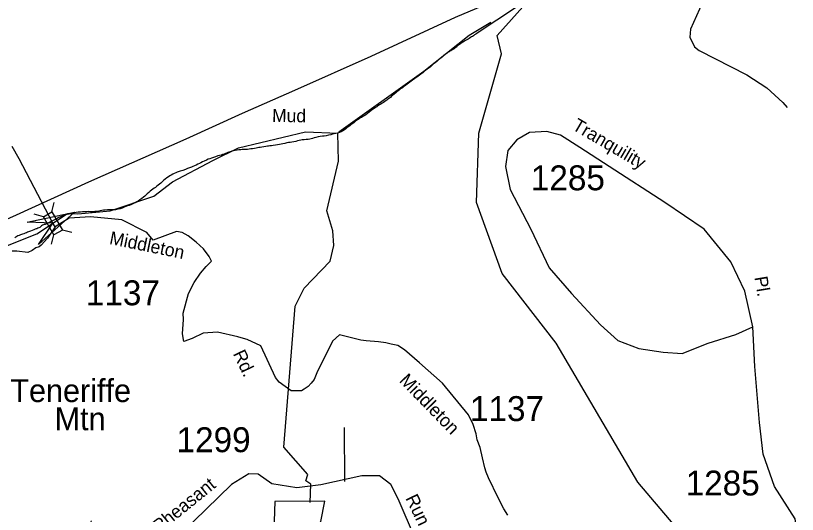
# Model space of a CAD drawing. Extents: x 884530 to 1028605, y 526725 to 653634.
# Drawn here: x 962593 to 966518, y 571686 to 574191 of the extents above; entities that cross this region are included whole.
import ezdxf

# ---------------------------------------------------------------- set-up
doc = ezdxf.new("R2010")
doc.units = 0
for name, color, linetype in [('Exist Boundary Political City Limit New', 7, 'Continuous'), ('Exist Geographical Mountain Summit Label', 7, 'Continuous'), ('Exist Hydrographic Bay Label', 7, 'Continuous'), ('Exist Hydrographic Creek Single Shore', 7, 'Continuous'), ('Exist Hydrographic Creek Single Shore Label', 7, 'Continuous'), ('Exist Road Non-System Type 51', 7, 'Continuous'), ('Exist Road Secondary Structure Standard Bridge Attributed CELL', 7, 'Continuous'), ('Exist Road Secondary Structure Standard Bridge CELL', 7, 'Continuous'), ('Exist Road Secondary Type 41 Attributed', 7, 'Continuous'), ('Exist Road Secondary Type 51 Attributed', 7, 'Continuous'), ('Exist Road Secondary Type 51 Label', 7, 'Continuous'), ('Exist Road Secondary Type 51 Number Label', 7, 'Continuous'), ('Exist Utilities Electrical Transmission Line', 7, 'Continuous'), ('Map Preparation Boundary City Limit Buffer Line', 7, 'Continuous')]:
    doc.layers.add(name, color=color, linetype=linetype)

msp = doc.modelspace()

# ---------------------------------------------------------------- linework, layer by layer
at = {"layer": 'Exist Boundary Political City Limit New'}
for points in [[(965107.1, 574233.1), (964910.9, 574103.4), (964908.8, 574101.8), (964903.6, 574098.1), (964897.6, 574094.1), (964891.6, 574090.1), (964886.4, 574086.7), (964881.7, 574083.8), (964876.3, 574080.5), (964870.5, 574077), (964864.4, 574073.3), (964858.1, 574069.4), (964852.1, 574065.7), (964846.6, 574062.4), (964842.1, 574059.9), (964834.9, 574055.7), (964826, 574049.9), (964816.9, 574043.4), (964808.9, 574037.1), (964804.4, 574033.1), (964799.5, 574029.1), (964794.4, 574024.9), (964788.8, 574020.9), (964783.7, 574017.7)], [(964783.7, 574017.7), (964778.6, 574014.8), (964773.8, 574012.1), (964769.8, 574009.9), (964765, 574007), (964759.5, 574003.2), (964754, 573999.1), (964749.1, 573995.2), (964742.8, 573990.2), (964736.1, 573984.9), (964729.2, 573979.1), (964722.4, 573973.6), (964714.7, 573967.2), (964707.6, 573961.4), (964700.9, 573955.9), (964695.1, 573950.9), (964690.2, 573946.5), (964684.6, 573941.6), (964678.9, 573936.6), (964673.8, 573932.4), (964669.2, 573929), (964664.2, 573925.4), (964658.7, 573921.4), (964653.1, 573917.3), (964645.9, 573911.7), (964639.1, 573906.1), (964632.8, 573900.9), (964627.2, 573896.4), (964620.4, 573891.4), (964612.2, 573885.8), (964603.9, 573880.1), (964596.7, 573874.9), (964591.3, 573870.9), (964585.4, 573866.4), (964579.2, 573861.6), (964572.8, 573856.7), (964565.6, 573851.4), (964558.4, 573846.4), (964551.6, 573841.6), (964545.5, 573837.2), (964540.5, 573833.5), (964534.9, 573829.2), (964529.4, 573825), (964524.5, 573821.3), (964519.3, 573817.4), (964513.6, 573813.1), (964507.4, 573808.3), (964501.2, 573803.3), (964494.2, 573797.3), (964487.4, 573791.4), (964480.9, 573785.8), (964474.9, 573780.7), (964470.4, 573777.1), (964465.3, 573773.2), (964460.4, 573769.6), (964456.2, 573766.4), (964451.6, 573763.1), (964446.1, 573759.4), (964440.1, 573755.4), (964433.5, 573751.1), (964426.7, 573746.8), (964420.2, 573742.6), (964414.7, 573739), (964410.7, 573736.4), (964406.2, 573733.6), (964400, 573729.5), (964392.6, 573724.7), (964384.7, 573719.4), (964376.1, 573712.6), (964367.6, 573705.9), (964359.3, 573699.6), (964351.2, 573693.6), (964346.1, 573690), (964340.3, 573686.2), (964334.8, 573682.9), (964330.1, 573680.2), (964325.1, 573677.5), (964319.2, 573674.1), (964313, 573670.1), (964306.6, 573665.8), (964298.2, 573659.4), (964290.4, 573653.1), (964283.2, 573647.1), (964276.8, 573641.9), (964270.6, 573637.4), (964263.4, 573632.1), (964256.2, 573626.8), (964250.2, 573621.9), (964243.8, 573616.9), (964236.2, 573612), (964227.8, 573607.5), (964218.5, 573603.6), (964209.2, 573600.8), (964200.1, 573598.5), (964191.7, 573596.8), (964184.6, 573595.2), (964175.3, 573593.1), (964164.1, 573590.6), (964152.6, 573588.1), (964142.4, 573586.2)], [(964142.4, 573586.2), (964133.1, 573584.9), (964122.8, 573583.4), (964111.9, 573581.6), (964100.7, 573579.1), (964092.4, 573576.8), (964084.5, 573574.4), (964077.2, 573572.2), (964071, 573570.6), (964062.4, 573569.4), (964052, 573568.5), (964041.3, 573567.8), (964031.9, 573566.9), (964024.8, 573565.6), (964017.1, 573563.8), (964008.9, 573561.6), (964000.4, 573559.6), (963990.4, 573557.6), (963980.6, 573555.9), (963971.3, 573554.5), (963962.9, 573553.2), (963954.1, 573551.6), (963944.4, 573549.5), (963934.8, 573547.2), (963926.6, 573545.2), (963918.1, 573543.4), (963908.4, 573541.8), (963897.7, 573540.2), (963886.5, 573538.7), (963878.2, 573537.7), (963870.3, 573536.8), (963863.2, 573535.9), (963857.1, 573535.2), (963849.2, 573534.1), (963839.8, 573532.5), (963829.9, 573530.8), (963821.2, 573529.2), (963814.8, 573528), (963807.6, 573526.8), (963800.1, 573525.5), (963792.2, 573524.2), (963782.8, 573522.8), (963773.6, 573521.4), (963765.1, 573520.2), (963757.8, 573519.2), (963752, 573518.8), (963745.1, 573518.4), (963738, 573518.2), (963731.4, 573518.1), (963723.1, 573517.8), (963714.4, 573517.1), (963705.4, 573515.9), (963696.2, 573514.2), (963686.9, 573512.2), (963677.9, 573509.8), (963669.8, 573507.4), (963662.9, 573505), (963658.1, 573503.1), (963652.2, 573500.8), (963648.8, 573499.4), (963646.1, 573498.2), (963640.1, 573496), (963632.4, 573493.4), (963624.6, 573491.1), (963616.6, 573488.8), (963608.2, 573486.3), (963597.1, 573482.7), (963586.1, 573478.9), (963576.2, 573475.3), (963568.2, 573472.4), (963560.4, 573469.4), (963550.8, 573465.3), (963540.6, 573460.7), (963531, 573456.2), (963523.6, 573452.5), (963516.1, 573448.8), (963508.2, 573444.9), (963499.4, 573440.8), (963491.1, 573437.1), (963482.9, 573433.5), (963476, 573430.5), (963471.6, 573428.6), (963465.9, 573426.1), (963456.8, 573422.6), (963445.5, 573418.4), (963433.1, 573413.9), (963426, 573411.6), (963419.4, 573409.4), (963413.8, 573407.7), (963409.6, 573406.4), (963404.2, 573404.4), (963397.1, 573401.4), (963389.4, 573397.9), (963382.1, 573394.4), (963374.6, 573390.6), (963367.3, 573386.2), (963360.1, 573381.3), (963352.8, 573376), (963344.3, 573369.2), (963336.1, 573362.4)], [(963336.1, 573362.4), (963328.5, 573355.9), (963322.1, 573350.2), (963316.2, 573345.2), (963309.3, 573339.6), (963302, 573333.8), (963295.2, 573328.5), (963289.1, 573323.9), (963282.7, 573319.1), (963276.1, 573314.1), (963269.2, 573308.7), (963261.4, 573302.3), (963253.8, 573295.9), (963247, 573289.9), (963241.4, 573284.8), (963234.6, 573279), (963226.1, 573272.2), (963217.2, 573265.5), (963209, 573259.6), (963201.8, 573255.2), (963193.6, 573251), (963184.9, 573247), (963175.8, 573243.2), (963162.9, 573238.2), (963150.4, 573233.4), (963138.4, 573229), (963127.4, 573224.9), (963117.4, 573221.6), (963106, 573218.7), (963094.7, 573216.4), (963084.8, 573215.2), (963075.6, 573215.1), (963065.2, 573215.2), (963053.9, 573215.2), (963042.3, 573214.6), (963033.8, 573213.5), (963025.7, 573212), (963018.2, 573210.4), (963011.6, 573209), (963002.2, 573207.6), (962990.9, 573206.8), (962979.6, 573206.5), (962969.9, 573206.5), (962961, 573206.6), (962951.1, 573206.4), (962940.4, 573206.2), (962929.4, 573205.7), (962918.4, 573204.9), (962907.8, 573204), (962897.9, 573202.8), (962889.3, 573201.5), (962880.8, 573199.7), (962870.9, 573197.2), (962861.1, 573194.7), (962852.4, 573192.5), (962844.6, 573190.4), (962836.1, 573187.7), (962827.3, 573184.6), (962818.6, 573181.1), (962813, 573178.6), (962807.7, 573176.1), (962802.4, 573173.6), (962801.2, 573172.9), (962748, 573145.1), (962745.8, 573144.4), (962741.1, 573142.9), (962737.4, 573141.9), (962735.3, 573141.8), (962732.6, 573141.1), (962728.1, 573138.6), (962722.4, 573134.6), (962714.9, 573127.4), (962709.2, 573124.9), (962704.2, 573122.9), (962700, 573121.2), (962696.9, 573120), (962691.6, 573118), (962684, 573115.2), (962675.6, 573112.2), (962667.9, 573109.3), (962663, 573107.3), (962657.9, 573105.2), (962652.8, 573103.1), (962647.4, 573100.8), (962640.7, 573098.1), (962634.1, 573095.6), (962627.9, 573093.3), (962622.5, 573091.5), (962617.3, 573089.7), (962611.2, 573087.3), (962605.1, 573084.6), (962599.5, 573081.8), (962594.3, 573078.8), (962589, 573075.6)]]:
    msp.add_lwpolyline(points, dxfattribs=at)
at = {"layer": 'Exist Hydrographic Bay Label'}
msp.add_lwpolyline([(964145.4, 571752.5), (963895.3, 571751), (963886.7, 571501.8), (963960.4, 571467.4), (964125.3, 571651.2), (964145.4, 571752.5)], dxfattribs=at)
at = {"layer": 'Exist Hydrographic Creek Single Shore'}
for points in [[(965010.2, 574091.4), (965183.7, 574284.8), (965300.3, 574522), (965726.4, 575750.6), (965964.1, 576592.5), (966026.5, 576949), (966132.9, 577137.2), (966219.1, 577693.3), (966231.4, 578050.8), (966207.3, 578077.6)], [(964216.4, 573608.3), (964641.8, 573911.3), (964870.6, 574092.3), (964979.6, 574157.7)], [(963262.4, 568538.8), (963374.9, 568694.6), (963495.8, 568936.4), (963563.6, 569637.7), (963663.2, 569868.7), (963818.3, 570013.2), (964200, 570199.2), (964528.8, 570547), (964715.3, 570631.8), (965137.9, 570551.1), (965803.3, 570501.6), (966013, 570536.8), (966277.8, 570718.4), (966340.3, 570841.9), (966347, 571032.2), (966277.2, 571187.8), (965716.4, 571848.9), (965306.9, 572546.3), (965035.6, 572896.3), (964906.2, 573253.3), (964918.3, 573601), (965032.1, 573999.1), (965010.2, 574091.4)], [(961437.8, 572523), (961676.2, 572652.8), (961845.2, 572755.5), (962699.4, 573095), (962853.3, 573197.6), (962905.3, 573195), (963068.7, 573210.2), (963286.6, 573284.3), (963380.3, 573356.3), (963582.9, 573463.1), (963711.5, 573526.3), (964049.2, 573608.3), (964210.6, 573601.1)], [(964071.3, 571746), (964074.6, 571837.8), (964050.2, 571854.7), (964059.6, 571887.4), (963939.2, 572024.3), (963997.1, 572732), (964042, 572823), (964171.9, 572958.2), (964190.8, 573037.5), (964186.5, 573109.5), (964155.4, 573211.2), (964214.1, 573459.4), (964210.6, 573601.1)]]:
    msp.add_lwpolyline(points, dxfattribs=at)
at = {"layer": 'Exist Road Non-System Type 51'}
msp.add_line((964246.7, 571851.3), (964244.7, 572122.3), dxfattribs=at)
msp.add_lwpolyline([(966061.9, 574300.9), (966042.3, 574257.4), (965981.5, 574122.9), (965978.6, 574082.7), (966000.7, 574033.9), (966024.6, 574016.7), (966264.7, 573893.1), (966364.4, 573827.9), (966444.9, 573755), (966466.9, 573729.3)], dxfattribs=at)
at = {"layer": 'Exist Road Secondary Structure Standard Bridge Attributed CELL'}
msp.add_lwpolyline([(962650.7, 573153.7), (962889.4, 573203.4), (962707.5, 573041), (962780.5, 573148.5)], close=True, dxfattribs=at)
at = {"layer": 'Exist Road Secondary Structure Standard Bridge CELL'}
for p, q in [((962774.5, 573205.5), (962787, 573252.1)), ((962732.7, 573181.3), (962686, 573193.8)), ((962772.9, 573042.9), (962785.4, 573089.6)), ((962874.8, 573101.8), (962828.2, 573114.3))]:
    msp.add_line(p, q, dxfattribs=at)
msp.add_lwpolyline([(962785.4, 573089.6), (962732.5, 573181.2), (962775.3, 573205.9), (962828.2, 573114.3)], close=True, dxfattribs=at)
at = {"layer": 'Exist Road Secondary Type 41 Attributed'}
for points in [[(962779.6, 573148.5), (962610.9, 573472.5), (962576.6, 573533.7)], [(962791, 573129.7), (962752.5, 573072.8), (962721.5, 573039.1), (962711.1, 573029.5), (962695.3, 573024.4), (962676.8, 573012.1), (962654.1, 573001.3), (962599.4, 573007.4), (962575.2, 573007.4)], [(962791, 573129.7), (962779.6, 573148.5)]]:
    msp.add_lwpolyline(points, dxfattribs=at)
at = {"layer": 'Exist Road Secondary Type 51 Attributed'}
for points in [[(966293.4, 572627.9), (966254.1, 572807.6), (966184.2, 572955.4), (966049.5, 573118.4), (965853, 573253.2), (965572.3, 573432.9), (965426.4, 573528.4), (965328.1, 573590.2), (965260.8, 573609.9), (965173.7, 573604.3), (965109.2, 573567.8)], [(965109.2, 573567.8), (965064.3, 573514.4), (965053, 573432.9), (965075.5, 573317.8), (965179.4, 573118.4), (965272, 572924.5), (965384.3, 572795.3), (965530.2, 572638), (965617.2, 572559.4), (965721.1, 572520.1), (965844.6, 572500.4), (965940, 572494.8), (966069.2, 572545.4), (966209.5, 572590.3), (966293.4, 572627.9)], [(965064.7, 571682), (965043.8, 571714.8), (965015.7, 571769.8), (964967.3, 571869.6), (964956.3, 571897.9), (964948.9, 571920.2), (964936.7, 571970.7), (964924.6, 572023.1), (964909.7, 572061.6), (964904.7, 572090.4), (964890.6, 572137.5), (964866.7, 572185.9), (964735.5, 572345.1), (964620.9, 572447.3), (964545.1, 572512.5), (964511.9, 572533.8), (964479.1, 572541.6), (964451.2, 572548.6), (964414.5, 572552.2), (964352.7, 572557.9), (964326.1, 572561.9), (964220, 572588.8), (964184.5, 572557), (964104.9, 572397.7), (964098.3, 572379.9), (964091.8, 572364.2), (964077, 572344.7), (964062.5, 572329.2), (964042, 572315.8), (964027.7, 572306.3), (963976.1, 572306.1), (963916.4, 572350.3), (963898.6, 572373.8), (963823.5, 572532), (963756.4, 572563.8), (963736.5, 572569.7), (963708.2, 572577.5), (963606.2, 572601.4), (963534.3, 572596), (963480.4, 572569.4), (963437.6, 572554.8), (963430.9, 572593.1), (963435.7, 572665.1), (963434.8, 572697.1), (963460.4, 572796.2), (963490.3, 572851.2), (963521.8, 572898.2), (963549.1, 572931.3), (963576.1, 572958.4), (963564.7, 572980.8), (963536.1, 573019.8), (963499.1, 573053.1), (963460.2, 573084.5), (963428.9, 573101.6), (963401, 573106.5), (963284.2, 573062.7), (963252.1, 573101.2), (963125.9, 573165.4), (962969.8, 573180.4), (962862.9, 573174), (962791, 573129.7)], [(966218.6, 570793.1), (966206.2, 570877.3), (966175.3, 571000.9), (966139.7, 571127.8), (966158.5, 571163.8), (966200.6, 571250.8), (966270.8, 571332.3), (966380.2, 571439), (966486.9, 571512.1), (966517.8, 571576.7), (966506.5, 571663.7), (966402.7, 571826.6), (966346.6, 571989.6), (966327.1, 572147.6), (966304.7, 572428.4), (966293.4, 572627.9)], [(964600.3, 571562), (964513.2, 571764.2), (964476.8, 571837.3), (964420.6, 571879.4), (964330.8, 571879.4), (964125.9, 571834.4), (964005.2, 571820.4), (963878.9, 571840.1), (963811.5, 571887.8), (963763.8, 571890.6), (963676.8, 571837.3), (963424.2, 571590.1), (963233.3, 571432.8), (963202.4, 571413.1), (963149.1, 571289.5), (963081.7, 571154.7), (962871.2, 571017.1), (962826.3, 571022.7), (962801, 571039.5), (962809.4, 571107), (962893.6, 571334.5), (962975, 571654.7)]]:
    msp.add_lwpolyline(points, dxfattribs=at)
at = {"layer": 'Exist Utilities Electrical Transmission Line'}
msp.add_lwpolyline([(965014.5, 574273.6), (964799.2, 574180.9), (964376.1, 573985.4), (963993.8, 573814.6), (963729.8, 573699.7), (963447.2, 573571.3), (962959.3, 573354.1), (962595.2, 573188.6), (962337.1, 573073.3)], dxfattribs=at)
at = {"layer": 'Map Preparation Boundary City Limit Buffer Line'}
for points in [[(965107.1, 574233.1), (964910.9, 574103.4), (964908.8, 574101.8), (964903.6, 574098.1), (964897.6, 574094.1), (964891.6, 574090.1), (964886.4, 574086.7), (964881.7, 574083.8), (964876.3, 574080.5), (964870.5, 574077), (964864.4, 574073.3), (964858.1, 574069.4), (964852.1, 574065.7), (964846.6, 574062.4), (964842.1, 574059.9), (964834.9, 574055.7), (964826, 574049.9), (964816.9, 574043.4), (964808.9, 574037.1), (964804.4, 574033.1), (964799.5, 574029.1), (964794.4, 574024.9), (964788.8, 574020.9), (964783.7, 574017.7)], [(964783.7, 574017.7), (964778.6, 574014.8), (964773.8, 574012.1), (964769.8, 574009.9), (964765, 574007), (964759.5, 574003.2), (964754, 573999.1), (964749.1, 573995.2), (964742.8, 573990.2), (964736.1, 573984.9), (964729.2, 573979.1), (964722.4, 573973.6), (964714.7, 573967.2), (964707.6, 573961.4), (964700.9, 573955.9), (964695.1, 573950.9), (964690.2, 573946.5), (964684.6, 573941.6), (964678.9, 573936.6), (964673.8, 573932.4), (964669.2, 573929), (964664.2, 573925.4), (964658.7, 573921.4), (964653.1, 573917.3), (964645.9, 573911.7), (964639.1, 573906.1), (964632.8, 573900.9), (964627.2, 573896.4), (964620.4, 573891.4), (964612.2, 573885.8), (964603.9, 573880.1), (964596.7, 573874.9), (964591.3, 573870.9), (964585.4, 573866.4), (964579.2, 573861.6), (964572.8, 573856.7), (964565.6, 573851.4), (964558.4, 573846.4), (964551.6, 573841.6), (964545.5, 573837.2), (964540.5, 573833.5), (964534.9, 573829.2), (964529.4, 573825), (964524.5, 573821.3), (964519.3, 573817.4), (964513.6, 573813.1), (964507.4, 573808.3), (964501.2, 573803.3), (964494.2, 573797.3), (964487.4, 573791.4), (964480.9, 573785.8), (964474.9, 573780.7), (964470.4, 573777.1), (964465.3, 573773.2), (964460.4, 573769.6), (964456.2, 573766.4), (964451.6, 573763.1), (964446.1, 573759.4), (964440.1, 573755.4), (964433.5, 573751.1), (964426.7, 573746.8), (964420.2, 573742.6), (964414.7, 573739), (964410.7, 573736.4), (964406.2, 573733.6), (964400, 573729.5), (964392.6, 573724.7), (964384.7, 573719.4), (964376.1, 573712.6), (964367.6, 573705.9), (964359.3, 573699.6), (964351.2, 573693.6), (964346.1, 573690), (964340.3, 573686.2), (964334.8, 573682.9), (964330.1, 573680.2), (964325.1, 573677.5), (964319.2, 573674.1), (964313, 573670.1), (964306.6, 573665.8), (964298.2, 573659.4), (964290.4, 573653.1), (964283.2, 573647.1), (964276.8, 573641.9), (964270.6, 573637.4), (964263.4, 573632.1), (964256.2, 573626.8), (964250.2, 573621.9), (964243.8, 573616.9), (964236.2, 573612), (964227.8, 573607.5), (964218.5, 573603.6), (964209.2, 573600.8), (964200.1, 573598.5), (964191.7, 573596.8), (964184.6, 573595.2), (964175.3, 573593.1), (964164.1, 573590.6), (964152.6, 573588.1), (964142.4, 573586.2)], [(964142.4, 573586.2), (964133.1, 573584.9), (964122.8, 573583.4), (964111.9, 573581.6), (964100.7, 573579.1), (964092.4, 573576.8), (964084.5, 573574.4), (964077.2, 573572.2), (964071, 573570.6), (964062.4, 573569.4), (964052, 573568.5), (964041.3, 573567.8), (964031.9, 573566.9), (964024.8, 573565.6), (964017.1, 573563.8), (964008.9, 573561.6), (964000.4, 573559.6), (963990.4, 573557.6), (963980.6, 573555.9), (963971.3, 573554.5), (963962.9, 573553.2), (963954.1, 573551.6), (963944.4, 573549.5), (963934.8, 573547.2), (963926.6, 573545.2), (963918.1, 573543.4), (963908.4, 573541.8), (963897.7, 573540.2), (963886.5, 573538.7), (963878.2, 573537.7), (963870.3, 573536.8), (963863.2, 573535.9), (963857.1, 573535.2), (963849.2, 573534.1), (963839.8, 573532.5), (963829.9, 573530.8), (963821.2, 573529.2), (963814.8, 573528), (963807.6, 573526.8), (963800.1, 573525.5), (963792.2, 573524.2), (963782.8, 573522.8), (963773.6, 573521.4), (963765.1, 573520.2), (963757.8, 573519.2), (963752, 573518.8), (963745.1, 573518.4), (963738, 573518.2), (963731.4, 573518.1), (963723.1, 573517.8), (963714.4, 573517.1), (963705.4, 573515.9), (963696.2, 573514.2), (963686.9, 573512.2), (963677.9, 573509.8), (963669.8, 573507.4), (963662.9, 573505), (963658.1, 573503.1), (963652.2, 573500.8), (963648.8, 573499.4), (963646.1, 573498.2), (963640.1, 573496), (963632.4, 573493.4), (963624.6, 573491.1), (963616.6, 573488.8), (963608.2, 573486.3), (963597.1, 573482.7), (963586.1, 573478.9), (963576.2, 573475.3), (963568.2, 573472.4), (963560.4, 573469.4), (963550.8, 573465.3), (963540.6, 573460.7), (963531, 573456.2), (963523.6, 573452.5), (963516.1, 573448.8), (963508.2, 573444.9), (963499.4, 573440.8), (963491.1, 573437.1), (963482.9, 573433.5), (963476, 573430.5), (963471.6, 573428.6), (963465.9, 573426.1), (963456.8, 573422.6), (963445.5, 573418.4), (963433.1, 573413.9), (963426, 573411.6), (963419.4, 573409.4), (963413.8, 573407.7), (963409.6, 573406.4), (963404.2, 573404.4), (963397.1, 573401.4), (963389.4, 573397.9), (963382.1, 573394.4), (963374.6, 573390.6), (963367.3, 573386.2), (963360.1, 573381.3), (963352.8, 573376), (963344.3, 573369.2), (963336.1, 573362.4)], [(963336.1, 573362.4), (963328.5, 573355.9), (963322.1, 573350.2), (963316.2, 573345.2), (963309.3, 573339.6), (963302, 573333.8), (963295.2, 573328.5), (963289.1, 573323.9), (963282.7, 573319.1), (963276.1, 573314.1), (963269.2, 573308.7), (963261.4, 573302.3), (963253.8, 573295.9), (963247, 573289.9), (963241.4, 573284.8), (963234.6, 573279), (963226.1, 573272.2), (963217.2, 573265.5), (963209, 573259.6), (963201.8, 573255.2), (963193.6, 573251), (963184.9, 573247), (963175.8, 573243.2), (963162.9, 573238.2), (963150.4, 573233.4), (963138.4, 573229), (963127.4, 573224.9), (963117.4, 573221.6), (963106, 573218.7), (963094.7, 573216.4), (963084.8, 573215.2), (963075.6, 573215.1), (963065.2, 573215.2), (963053.9, 573215.2), (963042.3, 573214.6), (963033.8, 573213.5), (963025.7, 573212), (963018.2, 573210.4), (963011.6, 573209), (963002.2, 573207.6), (962990.9, 573206.8), (962979.6, 573206.5), (962969.9, 573206.5), (962961, 573206.6), (962951.1, 573206.4), (962940.4, 573206.2), (962929.4, 573205.7), (962918.4, 573204.9), (962907.8, 573204), (962897.9, 573202.8), (962889.3, 573201.5), (962880.8, 573199.7), (962870.9, 573197.2), (962861.1, 573194.7), (962852.4, 573192.5), (962844.6, 573190.4), (962836.1, 573187.7), (962827.3, 573184.6), (962818.6, 573181.1), (962813, 573178.6), (962807.7, 573176.1), (962802.4, 573173.6), (962801.2, 573172.9), (962748, 573145.1), (962745.8, 573144.4), (962741.1, 573142.9), (962737.4, 573141.9), (962735.3, 573141.8), (962732.6, 573141.1), (962728.1, 573138.6), (962722.4, 573134.6), (962714.9, 573127.4), (962709.2, 573124.9), (962704.2, 573122.9), (962700, 573121.2), (962696.9, 573120), (962691.6, 573118), (962684, 573115.2), (962675.6, 573112.2), (962667.9, 573109.3), (962663, 573107.3), (962657.9, 573105.2), (962652.8, 573103.1), (962647.4, 573100.8), (962640.7, 573098.1), (962634.1, 573095.6), (962627.9, 573093.3), (962622.5, 573091.5), (962617.3, 573089.7), (962611.2, 573087.3), (962605.1, 573084.6), (962599.5, 573081.8), (962594.3, 573078.8), (962589, 573075.6)]]:
    msp.add_lwpolyline(points, dxfattribs=at)

# ---------------------------------------------------------------- texts
at = {"layer": 'Exist Geographical Mountain Summit Label'}
for s, p in [('Teneriffe', (962566.7, 572250.5)), ('Mtn', (962789.1, 572108.9))]:
    msp.add_text(s, height=114.83, dxfattribs=at).set_placement(p)
at = {"layer": 'Exist Hydrographic Creek Single Shore Label'}
msp.add_text('Mud', height=65.62, rotation=359.3456, dxfattribs=at).set_placement((963880.4, 573657.1))
msp.add_text('Mud', height=65.62, rotation=359.3456, dxfattribs=at).set_placement((963880.4, 573657.1))
at = {"layer": 'Exist Road Secondary Type 51 Label'}
for s, height, rotation, p in [('Tranquility', 65.617, 329.6478, (965383.1, 573622.3)), ('Middleton', 65.62, 348.457, (963060.5, 573044.6)), ('Pl.', 65.62, 279.2764, (966302.1, 572877.3)), ('Rd.', 65.62, 295.4108, (963682.9, 572493.7)), ('Middleton', 65.62, 314.2264, (964515.6, 572354.8)), ('Pheasant', 65.62, 39.0107, (963315.6, 571592.1)), ('Run', 65.62, 295.5924, (964548.8, 571768.3))]:
    msp.add_text(s, height=height, rotation=rotation, dxfattribs=at).set_placement(p)
at = {"layer": 'Exist Road Secondary Type 51 Number Label'}
for s, p in [('1285', (965179.8, 573314)), ('1137', (962945.7, 572736.6)), ('1137', (964874.1, 572155.1)), ('1299', (963401.3, 571998.8)), ('1285', (965956.9, 571781.3))]:
    msp.add_text(s, height=125, dxfattribs=at).set_placement(p)

doc.saveas('drawing.dxf')
